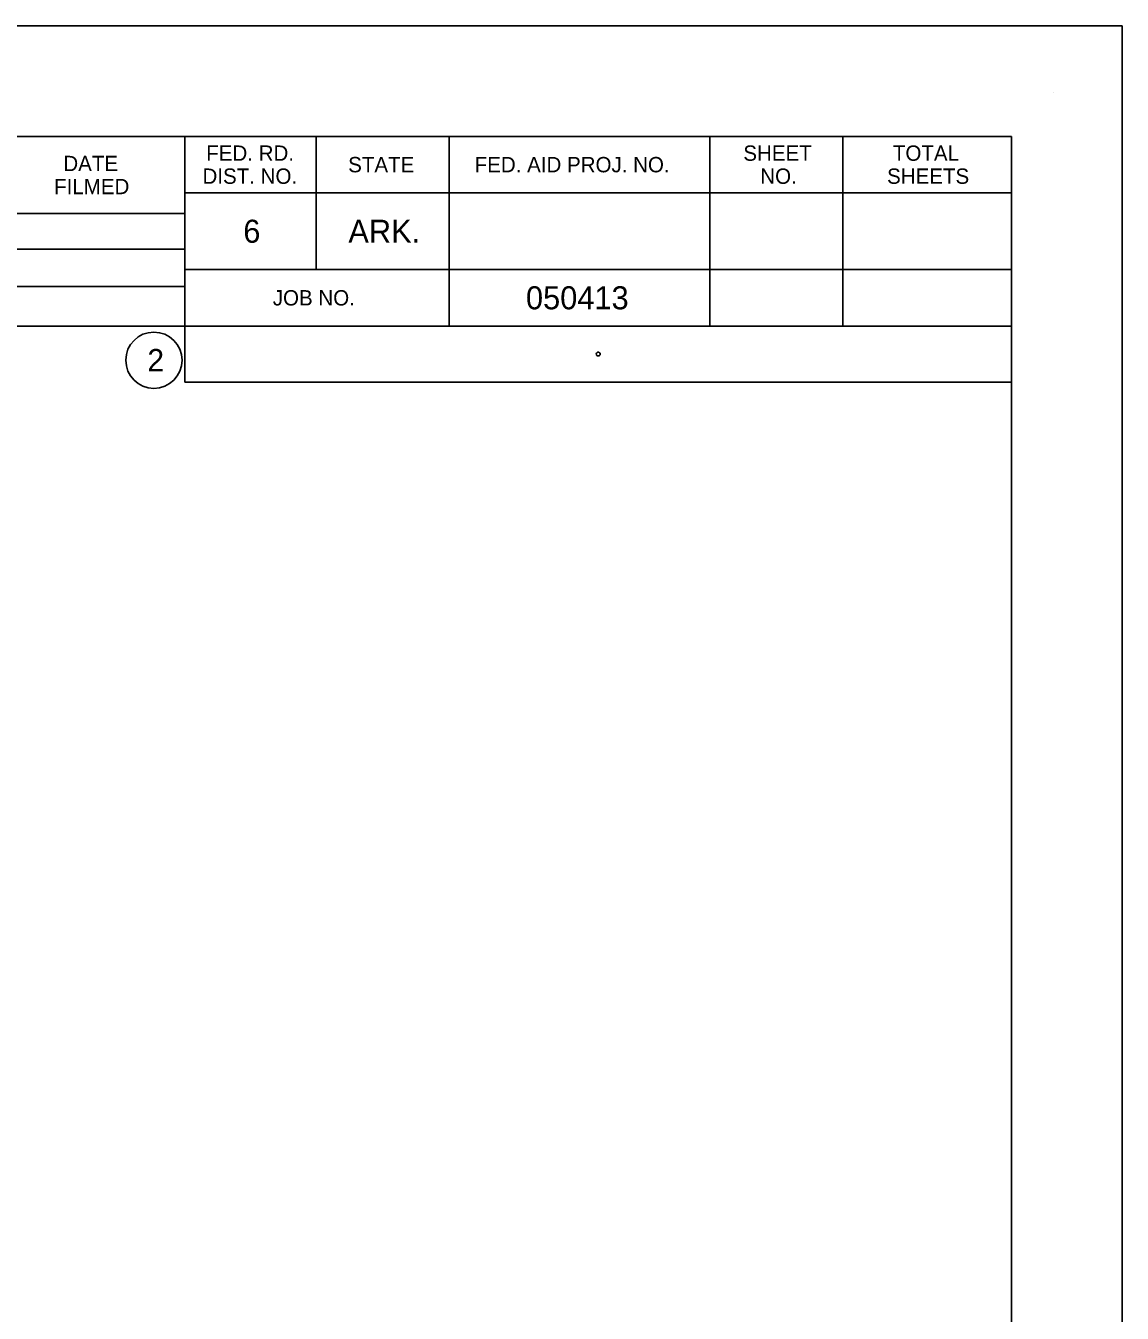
# Model space of a CAD drawing. Extents: x 759422 to 1467393, y 1662254 to 1691786.
# Drawn here: x 1466902.4 to 1467188.3, y 1691450.7 to 1691786.2 of the extents above; entities that cross this region are included whole.
import ezdxf

# ---------------------------------------------------------------- set-up
doc = ezdxf.new("R2010")
doc.units = 0
doc.layers.add('1', color=7, linetype='Continuous')
doc.layers.add('NO PLOT CELL', color=7, linetype='Continuous')

msp = doc.modelspace()

# ---------------------------------------------------------------- linework, layer by layer
at = {"layer": '1'}
for p, q in [((1467170.36, 1691768.89), (1467170.36, 1691768.89)), ((1465564.06, 1691757.36), (1467159.42, 1691757.36)), ((1466943.92, 1691757.36), (1466943.92, 1691693.36)), ((1466978.12, 1691757.36), (1466978.12, 1691722.66)), ((1467012.82, 1691757.36), (1467012.82, 1691707.96)), ((1467080.72, 1691757.36), (1467080.72, 1691707.96)), ((1467115.42, 1691757.36), (1467115.42, 1691707.96)), ((1467159.42, 1690715.04), (1467159.42, 1691757.36)), ((1467159.42, 1691742.66), (1466943.92, 1691742.66)), ((1467159.42, 1691742.76), (1467159.42, 1691742.76)), ((1466748.12, 1691737.26), (1466943.92, 1691737.26)), ((1466748.12, 1691727.96), (1466943.92, 1691727.96)), ((1467159.42, 1691722.66), (1466943.92, 1691722.66)), ((1466958.72, 1691722.66), (1467159.42, 1691722.66)), ((1466748.12, 1691718.26), (1466943.92, 1691718.26)), ((1467159.42, 1691707.96), (1466748.12, 1691707.96)), ((1466943.92, 1691693.36), (1467159.42, 1691693.36))]:
    msp.add_line(p, q, dxfattribs=at)
for points in [[(1467188.26, 1691786.2), (1465488.26, 1691786.2), (1465488.26, 1690686.2), (1467188.26, 1690686.2)], [(1465564.06, 1691757.36), (1465564.06, 1690715.04), (1467159.42, 1690715.04), (1467159.42, 1691693.36), (1466943.92, 1691693.36), (1466943.92, 1691707.96), (1466748.12, 1691707.96), (1466748.12, 1691757.36)]]:
    msp.add_lwpolyline(points, close=True, dxfattribs=at)
msp.add_circle((1466935.85, 1691699.04), 7.33, dxfattribs=at)
at = {"layer": 'NO PLOT CELL'}
msp.add_circle((1467051.67, 1691700.66), 0.5, dxfattribs=at)

# ---------------------------------------------------------------- texts
at = {"layer": '1'}
for s, height, p in [('FED. RD.', 4, (1466949.49, 1691751.01)), ('SHEET', 4, (1467089.49, 1691751.01)), ('TOTAL', 4, (1467128.47, 1691751.01)), ('DATE', 4, (1466912.25, 1691748.31)), ('STATE', 4, (1466986.49, 1691748.01)), ('FED. AID PROJ. NO.', 4, (1467019.46, 1691748.01)), ('DIST. NO.', 4, (1466948.52, 1691745.01)), ('NO.', 4, (1467093.91, 1691745.01)), ('SHEETS', 4, (1467126.96, 1691745.01)), ('FILMED', 4, (1466909.84, 1691742.31)), ('6', 6, (1466959.15, 1691729.66)), ('ARK.', 6, (1466986.54, 1691729.66)), ('050413', 6, (1467032.83, 1691712.31)), ('JOB NO.', 4, (1466966.84, 1691713.31)), ('2', 5.86, (1466934.15, 1691696.11))]:
    msp.add_text(s, height=height, dxfattribs=at).set_placement(p)

doc.saveas('drawing.dxf')
